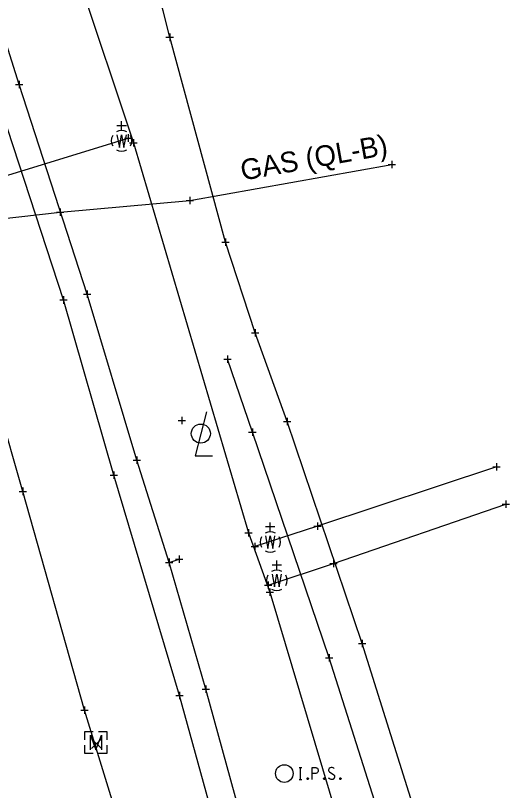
# Model space of a CAD drawing. Extents: x 2324380 to 2325559, y 691096 to 693386.
# Drawn here: x 2325090 to 2325157, y 692064.7 to 692170 of the extents above; entities that cross this region are included whole.
import ezdxf

# ---------------------------------------------------------------- set-up
doc = ezdxf.new("R2010")
doc.units = 0
for name, color, linetype in [('LT_X_Poles', 7, 'Continuous'), ('PM_X_Transverse_Line', 7, 'Continuous'), ('PV_X_COP', 7, 'Continuous'), ('PV_X_Driveway', 7, 'Continuous'), ('PV_X_EOP', 7, 'Continuous'), ('PV_X_Walk', 7, 'Continuous'), ('SV_P_Mon_Cells_Set', 7, 'Continuous'), ('SV_X_Mon_Cells_Found', 7, 'Continuous'), ('SV_X_Random_Point', 7, 'Continuous'), ('SV_X_Shot_Marker', 7, 'Continuous'), ('SV_X_Terrain_Boundary', 7, 'Continuous'), ('UT_X_Gas', 7, 'Continuous'), ('UT_X_Gas_Text', 7, 'Continuous'), ('UT_X_Water', 7, 'Continuous'), ('UT_X_Water_Cells', 7, 'Continuous')]:
    doc.layers.add(name, color=color, linetype=linetype)

msp = doc.modelspace()

# ---------------------------------------------------------------- linework, layer by layer
at = {"layer": 'LT_X_Poles'}
msp.add_lwpolyline([(2325115.93, 692116.14), (2325114.35, 692110.16), (2325116.71, 692110.16)], dxfattribs=at)
msp.add_circle((2325115.14, 692113.19), 1.3, dxfattribs=at)
at = {"layer": 'PM_X_Transverse_Line'}
msp.add_lwpolyline([(2325119.99, 692049.57), (2325112.24, 692077.64), (2325103.35, 692107.53), (2325096.49, 692131.33), (2325087.35, 692159.17), (2325078.82, 692186.21), (2325070.07, 692212.52), (2325061.8, 692237.43), (2325045.09, 692283.67), (2325035.69, 692308.59), (2325025.65, 692334.45)], dxfattribs=at)
at = {"layer": 'PV_X_COP'}
msp.add_lwpolyline([(2325108.45, 692046.03), (2325099.34, 692075.66), (2325091, 692105.35), (2325084.32, 692128.51), (2325075.39, 692156.76), (2325066.63, 692183.78), (2325058.11, 692209.28), (2325049.62, 692233.9), (2325041.55, 692256.48), (2325033.1, 692279.67), (2325023.32, 692305.87), (2325013.77, 692329.93)], dxfattribs=at)
at = {"layer": 'PV_X_Driveway'}
for p, q in [((2325110.91, 692166.99), (2325109.19, 692174.04)), ((2325118.5, 692139.18), (2325110.91, 692166.99)), ((2325122.51, 692126.86), (2325118.5, 692139.18)), ((2325110.86, 692095.71), (2325112.18, 692096.14))]:
    msp.add_line(p, q, dxfattribs=at)
at = {"layer": 'PV_X_EOP'}
msp.add_lwpolyline([(2325123.25, 692051.46), (2325115.82, 692078.51), (2325110.86, 692095.71), (2325106.46, 692109.57), (2325099.73, 692132.13), (2325090.5, 692160.58), (2325082.22, 692186.84), (2325072.77, 692213.83), (2325064.19, 692238.4), (2325059.92, 692251), (2325055.34, 692262.57), (2325047.32, 692284.59), (2325037.78, 692309.71), (2325028.4, 692335.51)], dxfattribs=at)
at = {"layer": 'PV_X_Walk'}
for points in [[(2325150.34, 692042.81), (2325145.29, 692058.32), (2325137.02, 692084.69), (2325126.84, 692114.85), (2325122.51, 692126.86)], [(2325145.41, 692042.34), (2325140.89, 692056.55), (2325132.56, 692082.73), (2325122.13, 692113.39), (2325118.75, 692123.3)]]:
    msp.add_lwpolyline(points, dxfattribs=at)
at = {"layer": 'SV_P_Mon_Cells_Set'}
for points in [[(2325128.48, 692067.84), (2325128.84, 692067.84)], [(2325128.66, 692066.24), (2325128.66, 692067.84)], [(2325130.23, 692066.24), (2325130.23, 692067.84), (2325130.76, 692067.84), (2325130.81, 692067.83), (2325130.89, 692067.8), (2325130.92, 692067.77), (2325130.95, 692067.75), (2325131, 692067.69), (2325131.03, 692067.62), (2325131.05, 692067.52), (2325131.05, 692067.37), (2325131.04, 692067.32), (2325131.02, 692067.25), (2325130.98, 692067.16), (2325130.93, 692067.12), (2325130.9, 692067.09), (2325130.84, 692067.07), (2325130.76, 692067.06), (2325130.23, 692067.06)], [(2325133.24, 692067.72), (2325133.21, 692067.75), (2325133.18, 692067.77), (2325133.08, 692067.81), (2325132.96, 692067.84), (2325132.87, 692067.84), (2325132.84, 692067.84), (2325132.7, 692067.8), (2325132.57, 692067.72), (2325132.5, 692067.62), (2325132.48, 692067.52), (2325132.48, 692067.45), (2325132.5, 692067.35), (2325132.59, 692067.26), (2325133.19, 692066.88), (2325133.25, 692066.83), (2325133.27, 692066.78), (2325133.29, 692066.7), (2325133.29, 692066.63), (2325133.28, 692066.55), (2325133.27, 692066.5), (2325133.25, 692066.44), (2325133.22, 692066.39), (2325133.2, 692066.35), (2325133.17, 692066.31), (2325133.14, 692066.29), (2325133.09, 692066.26), (2325133.06, 692066.25), (2325132.96, 692066.24), (2325132.81, 692066.24), (2325132.71, 692066.26), (2325132.56, 692066.35), (2325132.48, 692066.43)], [(2325128.48, 692066.24), (2325128.84, 692066.24)], [(2325129.62, 692066.45), (2325129.68, 692066.45), (2325129.71, 692066.43), (2325129.74, 692066.38), (2325129.74, 692066.31), (2325129.71, 692066.26), (2325129.68, 692066.24), (2325129.62, 692066.24), (2325129.59, 692066.26), (2325129.55, 692066.31), (2325129.55, 692066.38), (2325129.59, 692066.43), (2325129.62, 692066.45)], [(2325131.87, 692066.45), (2325131.92, 692066.45), (2325131.96, 692066.43), (2325131.99, 692066.38), (2325131.99, 692066.31), (2325131.96, 692066.26), (2325131.92, 692066.24), (2325131.87, 692066.24), (2325131.84, 692066.26), (2325131.8, 692066.31), (2325131.8, 692066.38), (2325131.84, 692066.43), (2325131.87, 692066.45)], [(2325134.05, 692066.45), (2325134.11, 692066.45), (2325134.14, 692066.43), (2325134.17, 692066.38), (2325134.17, 692066.31), (2325134.14, 692066.26), (2325134.11, 692066.24), (2325134.05, 692066.24), (2325134.02, 692066.26), (2325133.99, 692066.31), (2325133.99, 692066.38), (2325134.02, 692066.43), (2325134.05, 692066.45)]]:
    msp.add_lwpolyline(points, dxfattribs=at)
msp.add_circle((2325126.47, 692067.04), 1.2, dxfattribs=at)
at = {"layer": 'SV_X_Mon_Cells_Found'}
msp.add_line((2325100.9, 692071.26), (2325100.9, 692071.26), dxfattribs=at)
for points in [[(2325099.4, 692071.63), (2325099.4, 692072.76), (2325100.52, 692072.76)], [(2325101.25, 692072.76), (2325102.4, 692072.76), (2325102.4, 692071.63)], [(2325100.16, 692070.26), (2325100.16, 692072.26), (2325100.9, 692070.26), (2325101.64, 692072.26), (2325101.64, 692070.26)], [(2325100.52, 692069.76), (2325099.4, 692069.76), (2325099.4, 692070.88)], [(2325102.4, 692070.88), (2325102.4, 692069.76), (2325101.25, 692069.76)]]:
    msp.add_lwpolyline(points, dxfattribs=at)
at = {"layer": 'SV_X_Random_Point'}
for p, q in [((2325100.32, 692070.43), (2325101.65, 692071.77)), ((2325100.32, 692071.77), (2325101.65, 692070.43))]:
    msp.add_line(p, q, dxfattribs=at)
at = {"layer": 'SV_X_Shot_Marker'}
for p, q in [((2325110.91, 692167.49), (2325110.91, 692166.49)), ((2325110.41, 692166.99), (2325111.41, 692166.99)), ((2325110.91, 692166.99), (2325110.91, 692166.99)), ((2325090.5, 692161.08), (2325090.5, 692160.08)), ((2325090, 692160.58), (2325091, 692160.58)), ((2325090.5, 692160.58), (2325090.5, 692160.58)), ((2325105.29, 692153.82), (2325105.29, 692152.82)), ((2325104.79, 692153.32), (2325105.79, 692153.32)), ((2325105.29, 692153.32), (2325105.29, 692153.32)), ((2325105.48, 692152.66), (2325106.48, 692152.66)), ((2325105.98, 692153.16), (2325105.98, 692152.16)), ((2325105.98, 692152.66), (2325105.98, 692152.66)), ((2325140.56, 692149.71), (2325141.56, 692149.71)), ((2325141.06, 692150.21), (2325141.06, 692149.21)), ((2325141.06, 692149.71), (2325141.06, 692149.71)), ((2325113.64, 692145.33), (2325113.64, 692144.33)), ((2325113.14, 692144.83), (2325114.14, 692144.83)), ((2325113.64, 692144.83), (2325113.64, 692144.83)), ((2325095.57, 692143.24), (2325096.57, 692143.24)), ((2325096.07, 692143.74), (2325096.07, 692142.74)), ((2325096.07, 692143.24), (2325096.07, 692143.24)), ((2325118, 692139.18), (2325119, 692139.18)), ((2325118.5, 692139.68), (2325118.5, 692138.68)), ((2325118.5, 692139.18), (2325118.5, 692139.18)), ((2325099.73, 692132.63), (2325099.73, 692131.63)), ((2325096.49, 692131.83), (2325096.49, 692130.83)), ((2325099.23, 692132.13), (2325100.23, 692132.13)), ((2325099.73, 692132.13), (2325099.73, 692132.13)), ((2325095.99, 692131.33), (2325096.99, 692131.33)), ((2325096.49, 692131.33), (2325096.49, 692131.33)), ((2325122.51, 692127.36), (2325122.51, 692126.36)), ((2325122.51, 692127.36), (2325122.51, 692126.36)), ((2325122.01, 692126.86), (2325123.01, 692126.86)), ((2325122.01, 692126.86), (2325123.01, 692126.86)), ((2325122.51, 692126.86), (2325122.51, 692126.86)), ((2325122.51, 692126.86), (2325122.51, 692126.86)), ((2325118.25, 692123.3), (2325119.25, 692123.3)), ((2325118.75, 692123.8), (2325118.75, 692122.8)), ((2325118.75, 692123.3), (2325118.75, 692123.3)), ((2325112.07, 692114.96), (2325113.07, 692114.96)), ((2325112.57, 692115.46), (2325112.57, 692114.46)), ((2325112.57, 692114.96), (2325112.57, 692114.96)), ((2325126.34, 692114.85), (2325127.34, 692114.85)), ((2325126.84, 692115.35), (2325126.84, 692114.35)), ((2325126.84, 692114.85), (2325126.84, 692114.85)), ((2325122.13, 692113.89), (2325122.13, 692112.89)), ((2325121.63, 692113.39), (2325122.63, 692113.39)), ((2325122.13, 692113.39), (2325122.13, 692113.39)), ((2325105.96, 692109.57), (2325106.96, 692109.57)), ((2325106.46, 692110.07), (2325106.46, 692109.07)), ((2325106.46, 692109.57), (2325106.46, 692109.57)), ((2325154.78, 692108.68), (2325155.78, 692108.68)), ((2325155.28, 692109.18), (2325155.28, 692108.18)), ((2325155.28, 692108.68), (2325155.28, 692108.68)), ((2325102.85, 692107.53), (2325103.85, 692107.53)), ((2325103.35, 692108.03), (2325103.35, 692107.03)), ((2325103.35, 692107.53), (2325103.35, 692107.53)), ((2325090.5, 692105.35), (2325091.5, 692105.35)), ((2325091, 692105.85), (2325091, 692104.85)), ((2325091, 692105.35), (2325091, 692105.35)), ((2325156.52, 692104.11), (2325156.52, 692103.11)), ((2325156.02, 692103.61), (2325157.02, 692103.61)), ((2325156.52, 692103.61), (2325156.52, 692103.61)), ((2325130.96, 692101.14), (2325130.96, 692100.14)), ((2325121.62, 692100.23), (2325121.62, 692099.23)), ((2325130.46, 692100.64), (2325131.46, 692100.64)), ((2325130.96, 692100.64), (2325130.96, 692100.64)), ((2325121.12, 692099.73), (2325122.12, 692099.73)), ((2325121.62, 692099.73), (2325121.62, 692099.73)), ((2325121.97, 692097.86), (2325122.97, 692097.86)), ((2325122.47, 692098.36), (2325122.47, 692097.36)), ((2325122.47, 692097.86), (2325122.47, 692097.86)), ((2325110.36, 692095.71), (2325111.36, 692095.71)), ((2325110.36, 692095.71), (2325111.36, 692095.71)), ((2325110.86, 692096.21), (2325110.86, 692095.21)), ((2325110.86, 692096.21), (2325110.86, 692095.21)), ((2325110.86, 692095.71), (2325110.86, 692095.71)), ((2325110.86, 692095.71), (2325110.86, 692095.71)), ((2325111.68, 692096.14), (2325112.68, 692096.14)), ((2325112.18, 692096.64), (2325112.18, 692095.64)), ((2325112.18, 692096.14), (2325112.18, 692096.14)), ((2325133.13, 692096.06), (2325133.13, 692095.06)), ((2325132.63, 692095.56), (2325133.63, 692095.56)), ((2325133.13, 692095.56), (2325133.13, 692095.56)), ((2325123.77, 692092.62), (2325124.77, 692092.62)), ((2325124.27, 692093.12), (2325124.27, 692092.12)), ((2325124.27, 692092.62), (2325124.27, 692092.62)), ((2325124.02, 692091.67), (2325125.02, 692091.67)), ((2325124.52, 692092.17), (2325124.52, 692091.17)), ((2325124.52, 692091.67), (2325124.52, 692091.67)), ((2325137.02, 692085.19), (2325137.02, 692084.19)), ((2325136.52, 692084.69), (2325137.52, 692084.69)), ((2325137.02, 692084.69), (2325137.02, 692084.69)), ((2325132.56, 692083.23), (2325132.56, 692082.23)), ((2325132.06, 692082.73), (2325133.06, 692082.73)), ((2325132.56, 692082.73), (2325132.56, 692082.73)), ((2325115.82, 692079.01), (2325115.82, 692078.01)), ((2325112.24, 692078.14), (2325112.24, 692077.14)), ((2325115.32, 692078.51), (2325116.32, 692078.51)), ((2325115.82, 692078.51), (2325115.82, 692078.51)), ((2325111.74, 692077.64), (2325112.74, 692077.64)), ((2325112.24, 692077.64), (2325112.24, 692077.64)), ((2325099.34, 692076.16), (2325099.34, 692075.16)), ((2325098.84, 692075.66), (2325099.84, 692075.66)), ((2325099.34, 692075.66), (2325099.34, 692075.66))]:
    msp.add_line(p, q, dxfattribs=at)
at = {"layer": 'SV_X_Terrain_Boundary'}
msp.add_lwpolyline([(2325145.29, 692058.32), (2325137.02, 692084.69), (2325126.84, 692114.85), (2325122.51, 692126.86), (2325118.5, 692139.18), (2325110.91, 692166.99), (2325109.19, 692174.04)], dxfattribs=at)
at = {"layer": 'UT_X_Gas'}
msp.add_lwpolyline([(2325064.33, 692139.67), (2325096.07, 692143.24), (2325113.64, 692144.83), (2325141.06, 692149.71)], dxfattribs=at)
at = {"layer": 'UT_X_Water'}
for points in [[(2324934.92, 692571.2), (2324956.29, 692529.58), (2324976.21, 692488), (2324991.94, 692453.33), (2325012.4, 692405.82), (2325031.94, 692356.27), (2325051.28, 692307.99), (2325065.92, 692268.22), (2325079.64, 692231.2), (2325091.06, 692197.41), (2325105.98, 692152.66), (2325121.62, 692099.73), (2325124.52, 692091.67), (2325134.64, 692057.74)], [(2325004.14, 692109.95), (2325033.21, 692130.96), (2325063.32, 692140.41), (2325105.29, 692153.32)], [(2325155.28, 692108.68), (2325130.96, 692100.64), (2325122.47, 692097.86)], [(2325124.27, 692092.62), (2325133.13, 692095.56), (2325156.52, 692103.61)]]:
    msp.add_lwpolyline(points, dxfattribs=at)
at = {"layer": 'UT_X_Water_Cells'}
for p, q in [((2325105.03, 692154.98), (2325103.76, 692154.98)), ((2325104.39, 692154.35), (2325104.39, 692155.62)), ((2325104.39, 692152.95), (2325104.39, 692152.95)), ((2325124.57, 692099.87), (2325124.57, 692101.14)), ((2325125.2, 692100.51), (2325123.93, 692100.51)), ((2325124.57, 692098.47), (2325124.57, 692098.47)), ((2325125.44, 692094.67), (2325125.44, 692095.94)), ((2325126.07, 692095.31), (2325124.8, 692095.31)), ((2325125.44, 692093.27), (2325125.44, 692093.27))]:
    msp.add_line(p, q, dxfattribs=at)
for points in [[(2325103.76, 692153.77), (2325104.08, 692152.04), (2325104.39, 692153.77), (2325104.71, 692152.04), (2325105.03, 692153.77)], [(2325123.93, 692099.29), (2325124.25, 692097.57), (2325124.57, 692099.29), (2325124.89, 692097.57), (2325125.2, 692099.29)], [(2325124.8, 692094.09), (2325125.12, 692092.37), (2325125.44, 692094.09), (2325125.76, 692092.37), (2325126.07, 692094.09)]]:
    msp.add_lwpolyline(points, dxfattribs=at)
for centre, start, end in [((2325104.39, 692152.95), 150.0184, 209.9816), ((2325104.39, 692152.95), 60.0184, 120.0157), ((2325104.39, 692152.95), 330.0184, 29.9816), ((2325104.39, 692152.95), 239.9843, 299.9816), ((2325124.57, 692098.47), 60.0184, 120.0157), ((2325124.57, 692098.47), 150.0184, 209.9816), ((2325124.57, 692098.47), 330.0184, 29.9816), ((2325124.57, 692098.47), 239.9843, 299.9816), ((2325125.44, 692093.27), 60.0184, 120.0157), ((2325125.44, 692093.27), 150.0184, 209.9816), ((2325125.44, 692093.27), 330.0184, 29.9816), ((2325125.44, 692093.27), 239.9843, 299.9816)]:
    msp.add_arc(centre, 1.4, start, end, dxfattribs=at)

# ---------------------------------------------------------------- texts
at = {"layer": 'UT_X_Gas_Text'}
msp.add_text('GAS (QL-B)', height=2.8, rotation=10.08, dxfattribs=at).set_placement((2325120.79, 692147.53))

doc.saveas('drawing.dxf')
